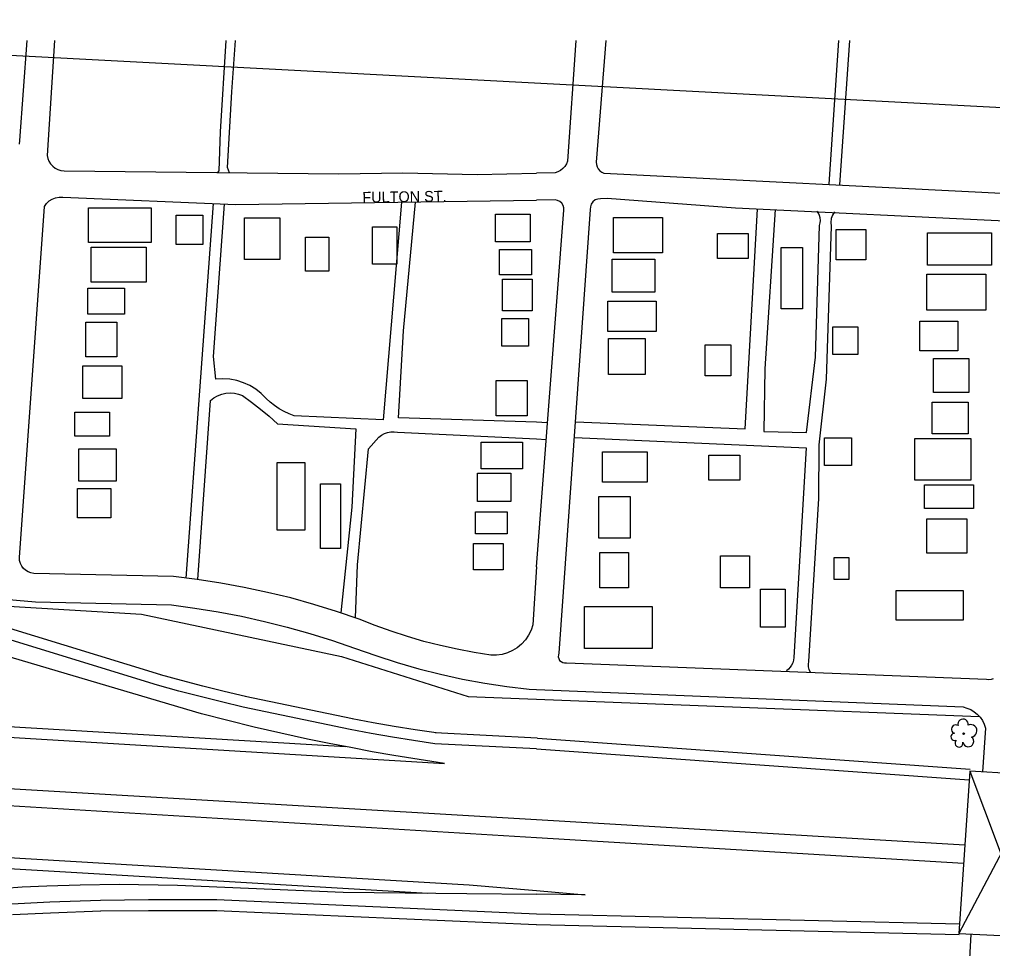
# Model space of a CAD drawing. Extents: x -9648 to 41057, y -12373 to 40276.
# Drawn here: x 16567 to 17468, y -5297 to -4437 of the extents above; entities that cross this region are included whole.
import ezdxf

# ---------------------------------------------------------------- set-up
doc = ezdxf.new("R2010")
doc.units = 0
doc.layers.add('SC_Scratch1', color=7, linetype='Continuous')
doc.layers.add('SH_Data', color=7, linetype='Continuous')

msp = doc.modelspace()

# ---------------------------------------------------------------- linework, layer by layer
at = {"layer": 'SC_Scratch1'}
for p, q in [((17512.22, -4520.66), (15927.4, -4436.94)), ((17447.28, -5132.46), (17504.68, -5286.06)), ((17514.08, -5136.46), (17436.88, -5282.86))]:
    msp.add_line(p, q, dxfattribs=at)
at = {"layer": 'SH_Data'}
for p, q in [((16567.48, -4548.86), (16574.48, -4456.26)), ((16599.68, -4456.26), (16592.88, -4562.66)), ((16758.28, -4456.26), (16753.08, -4540.86)), ((16763.88, -4503.86), (16767.28, -4456.26)), ((17082.28, -4456.26), (17074.68, -4568.06)), ((17110.08, -4456.26), (17101.28, -4568.86)), ((17325.48, -4456.26), (17316.48, -4589.46)), ((17326.68, -4589.96), (17336.08, -4456.26)), ((16759.98, -4573.76), (16763.88, -4503.86)), ((16567.18, -4552.26), (16567.48, -4548.86)), ((16753.08, -4540.86), (16751.88, -4577.06)), ((16592.88, -4562.66), (16593.48, -4565.46)), ((16593.48, -4565.46), (16594.48, -4568.16)), ((16594.48, -4568.16), (16596.08, -4570.66)), ((16596.08, -4570.66), (16597.98, -4572.76)), ((16597.98, -4572.76), (16600.28, -4574.56)), ((16600.28, -4574.56), (16602.88, -4575.86)), ((16602.88, -4575.86), (16605.58, -4576.76)), ((16605.58, -4576.76), (16608.48, -4577.06)), ((16761.58, -4578.76), (16759.98, -4573.76)), ((17068.18, -4576.56), (17065.78, -4577.86)), ((17070.28, -4574.86), (17068.18, -4576.56)), ((17072.08, -4572.86), (17070.28, -4574.86)), ((17073.58, -4570.56), (17072.08, -4572.86)), ((17074.68, -4568.06), (17073.58, -4570.56)), ((17101.28, -4568.86), (17101.48, -4571.06)), ((17101.48, -4571.06), (17102.18, -4573.16)), ((17102.18, -4573.16), (17103.18, -4575.16)), ((17103.18, -4575.16), (17104.68, -4576.86)), ((16608.48, -4577.06), (16862.88, -4579.86)), ((16751.88, -4577.06), (16750.48, -4578.66)), ((16862.88, -4579.86), (16922.28, -4578.86)), ((16922.28, -4578.86), (16991.08, -4580.26)), ((16991.08, -4580.26), (17046.08, -4579.26)), ((17063.28, -4578.86), (17046.08, -4579.26)), ((17065.78, -4577.86), (17063.28, -4578.86)), ((17104.68, -4576.86), (17106.38, -4578.26)), ((17106.38, -4578.26), (17108.38, -4579.16)), ((17108.38, -4579.16), (17494.08, -4598.66)), ((16594.68, -4604.86), (16597.58, -4603.16)), ((16597.58, -4603.16), (16600.68, -4601.96)), ((16600.68, -4601.96), (16603.98, -4601.36)), ((16603.98, -4601.36), (16607.28, -4601.46)), ((16607.28, -4601.46), (16767.68, -4608.26)), ((17102.68, -4603.06), (17100.18, -4603.96)), ((17105.28, -4602.86), (17102.68, -4603.06)), ((17111.28, -4602.66), (17105.28, -4602.86)), ((17230.28, -4611.66), (17111.28, -4602.66)), ((16567.28, -4934.86), (16590.28, -4609.86)), ((16590.28, -4609.86), (16592.28, -4607.16)), ((16592.28, -4607.16), (16594.68, -4604.86)), ((16746.68, -4607.36), (16721.28, -4953.86)), ((16746.88, -4748.66), (16757.08, -4607.86)), ((16767.68, -4608.26), (17046.08, -4604.26)), ((16921.08, -4606.06), (16903.88, -4807.26)), ((16922.88, -4725.06), (16933.88, -4605.96)), ((17063.28, -4603.86), (17046.08, -4604.26)), ((17065.48, -4604.36), (17063.28, -4603.86)), ((17067.58, -4605.46), (17065.48, -4604.36)), ((17069.28, -4607.06), (17067.58, -4605.46)), ((17070.48, -4608.96), (17069.28, -4607.06)), ((17071.18, -4611.16), (17070.48, -4608.96)), ((17071.28, -4613.46), (17071.18, -4611.16)), ((17095.78, -4610.26), (17095.68, -4612.86)), ((17096.58, -4607.76), (17095.78, -4610.26)), ((17098.18, -4605.56), (17096.58, -4607.76)), ((17100.18, -4603.96), (17098.18, -4605.56)), ((17485.88, -4623.96), (17230.28, -4611.66)), ((17239.08, -4815.66), (17250.48, -4612.36)), ((17046.08, -4943.46), (17071.28, -4613.46)), ((17095.68, -4612.86), (17066.68, -5023.26)), ((17266.88, -4612.86), (17257.28, -4760.06)), ((17306.88, -4616.26), (17305.58, -4614.36)), ((17307.88, -4618.36), (17306.88, -4616.26)), ((17308.58, -4620.56), (17307.88, -4618.36)), ((17308.78, -4622.86), (17308.58, -4620.56)), ((17318.78, -4621.16), (17318.38, -4624.66)), ((17319.98, -4617.96), (17318.78, -4621.16)), ((17321.88, -4615.06), (17319.98, -4617.96)), ((17304.28, -4749.46), (17308.08, -4627.46)), ((17308.08, -4627.46), (17308.68, -4625.16)), ((17308.68, -4625.16), (17308.78, -4622.86)), ((17318.68, -4628.06), (17314.08, -4769.66)), ((17318.38, -4624.66), (17318.68, -4628.06)), ((16918.08, -4805.46), (16922.88, -4725.06)), ((16749.08, -4769.66), (16746.88, -4748.66)), ((17295.88, -4819.06), (17304.28, -4749.46)), ((17257.28, -4760.06), (17256.28, -4818.26)), ((16755.58, -4769.36), (16749.08, -4769.66)), ((16761.98, -4769.86), (16755.58, -4769.36)), ((16768.38, -4771.06), (16761.98, -4769.86)), ((16774.58, -4773.06), (16768.38, -4771.06)), ((16780.48, -4775.76), (16774.58, -4773.06)), ((17314.08, -4769.66), (17307.28, -4830.46)), ((16750.68, -4785.16), (16754.48, -4783.76)), ((16754.48, -4783.76), (16758.28, -4782.86)), ((16758.28, -4782.86), (16762.28, -4782.56)), ((16762.28, -4782.56), (16766.28, -4782.76)), ((16766.28, -4782.76), (16770.18, -4783.56)), ((16770.18, -4783.56), (16773.88, -4784.86)), ((16785.98, -4779.16), (16780.48, -4775.76)), ((16791.08, -4783.06), (16785.98, -4779.16)), ((16795.68, -4787.66), (16791.08, -4783.06)), ((16732.28, -4955.16), (16744.08, -4789.46)), ((16744.08, -4789.46), (16747.28, -4787.06)), ((16747.28, -4787.06), (16750.68, -4785.16)), ((16773.88, -4784.86), (16782.18, -4791.06)), ((16782.18, -4791.06), (16790.38, -4797.56)), ((16799.48, -4791.16), (16795.68, -4787.66)), ((16803.48, -4794.26), (16799.48, -4791.16)), ((16790.38, -4797.56), (16798.28, -4804.16)), ((16807.78, -4797.16), (16803.48, -4794.26)), ((16812.28, -4799.66), (16807.78, -4797.16)), ((16816.88, -4801.86), (16812.28, -4799.66)), ((16821.68, -4803.66), (16816.88, -4801.86)), ((16798.28, -4804.16), (16806.08, -4811.06)), ((16903.88, -4807.26), (16821.68, -4803.66)), ((17046.08, -4809.66), (16918.08, -4805.46)), ((17055.88, -4810.06), (17046.08, -4809.66)), ((17082.38, -4809.26), (17239.08, -4815.66)), ((16806.08, -4811.06), (16878.78, -4815.66)), ((16878.78, -4815.66), (16874.88, -4888.26)), ((16905.08, -4820.06), (16908.08, -4819.06)), ((16908.08, -4819.06), (16911.08, -4818.56)), ((16911.08, -4818.56), (16914.18, -4818.46)), ((16914.18, -4818.46), (16917.28, -4818.86)), ((16917.28, -4818.86), (17046.08, -4825.06)), ((17256.28, -4818.26), (17295.88, -4819.06)), ((16890.28, -4834.26), (16899.88, -4823.46)), ((16899.88, -4823.46), (16902.38, -4821.56)), ((16902.38, -4821.56), (16905.08, -4820.06)), ((17046.08, -4825.06), (17054.78, -4825.46)), ((17081.28, -4823.66), (17295.68, -4833.46)), ((16880.08, -4941.46), (16890.28, -4834.26)), ((17295.68, -4833.46), (17284.28, -5027.46)), ((17307.28, -4830.46), (17306.88, -4880.06)), ((17306.88, -4880.06), (17297.88, -5031.06)), ((16874.88, -4888.26), (16864.68, -4986.06)), ((16567.38, -4937.56), (16567.28, -4934.86)), ((16193.48, -4944.86), (16582.08, -4975.66)), ((16568.08, -4940.26), (16567.38, -4937.56)), ((16569.28, -4942.66), (16568.08, -4940.26)), ((16570.88, -4944.86), (16569.28, -4942.66)), ((16572.88, -4946.66), (16570.88, -4944.86)), ((16878.48, -4990.76), (16880.08, -4941.46)), ((17046.08, -4943.46), (17042.48, -4997.06)), ((16575.18, -4948.16), (16572.88, -4946.66)), ((16577.78, -4949.06), (16575.18, -4948.16)), ((16580.48, -4949.46), (16577.78, -4949.06)), ((16709.88, -4952.46), (16580.48, -4949.46)), ((16731.78, -4955.16), (16709.88, -4952.46)), ((16753.68, -4958.46), (16731.78, -4955.16)), ((16775.38, -4962.46), (16753.68, -4958.46)), ((16796.98, -4967.06), (16775.38, -4962.46)), ((16435.85, -4972.35), (16680.32, -4987.24)), ((16818.38, -4972.26), (16796.98, -4967.06)), ((16839.68, -4978.16), (16818.38, -4972.26)), ((16582.08, -4975.66), (16708.08, -4978.66)), ((16708.08, -4978.66), (16729.68, -4981.56)), ((16729.68, -4981.56), (16751.18, -4985.06)), ((16860.78, -4984.76), (16839.68, -4978.16)), ((16680.32, -4987.24), (16865.25, -5026.43)), ((16751.18, -4985.06), (16772.68, -4989.16)), ((16772.68, -4989.16), (16793.98, -4993.86)), ((16881.68, -4991.86), (16860.78, -4984.76)), ((16698.01, -5043.5), (16550.21, -4998.1)), ((16793.98, -4993.86), (16815.08, -4999.16)), ((16815.08, -4999.16), (16836.08, -5005.06)), ((16896.48, -4997.66), (16881.68, -4991.86)), ((16911.38, -5002.96), (16896.48, -4997.66)), ((17042.48, -4997.06), (17040.88, -5001.96)), ((16695.08, -5053.06), (16547.28, -5007.66)), ((16836.08, -5005.06), (16856.98, -5011.56)), ((16926.48, -5007.86), (16911.38, -5002.96)), ((16941.68, -5012.36), (16926.48, -5007.86)), ((17038.58, -5006.66), (17035.68, -5010.96)), ((17040.88, -5001.96), (17038.58, -5006.66)), ((16856.98, -5011.56), (16877.58, -5018.56)), ((16956.98, -5016.26), (16941.68, -5012.36)), ((16972.48, -5019.76), (16956.98, -5016.26)), ((17032.18, -5014.86), (17028.18, -5018.26)), ((17035.68, -5010.96), (17032.18, -5014.86)), ((16735.68, -5079.46), (16553.28, -5025.46)), ((16865.25, -5026.43), (16982.78, -5063.27)), ((16877.58, -5018.56), (16897.18, -5025.56)), ((16897.18, -5025.56), (16916.98, -5031.96)), ((16988.08, -5022.76), (16972.48, -5019.76)), ((17003.68, -5025.26), (16988.08, -5022.76)), ((17008.88, -5025.26), (17003.68, -5025.26)), ((17014.08, -5024.56), (17008.88, -5025.26)), ((17019.08, -5023.06), (17014.08, -5024.56)), ((17023.78, -5020.96), (17019.08, -5023.06)), ((17028.18, -5018.26), (17023.78, -5020.96)), ((17066.18, -5024.96), (17066.08, -5026.66)), ((17066.08, -5026.66), (17066.48, -5028.36)), ((17066.68, -5023.26), (17066.18, -5024.96)), ((16916.98, -5031.96), (16936.98, -5037.66)), ((17066.48, -5028.36), (17067.38, -5029.96)), ((17067.38, -5029.96), (17068.68, -5031.16)), ((17068.68, -5031.16), (17070.18, -5031.96)), ((17070.18, -5031.96), (17071.88, -5032.36)), ((17071.88, -5032.36), (17073.68, -5032.26)), ((17073.68, -5032.26), (17462.68, -5047.46)), ((17280.88, -5036.26), (17279.18, -5038.06)), ((17282.18, -5034.36), (17280.88, -5036.26)), ((17283.18, -5032.16), (17282.18, -5034.36)), ((17283.98, -5029.86), (17283.18, -5032.16)), ((17284.28, -5027.46), (17283.98, -5029.86)), ((17297.88, -5031.06), (17297.48, -5033.46)), ((17297.48, -5033.46), (17297.58, -5035.96)), ((17297.58, -5035.96), (17298.18, -5038.36)), ((16717.37, -5048.71), (16697.67, -5043.41)), ((16936.98, -5037.66), (16957.18, -5042.76)), ((16957.18, -5042.76), (16977.48, -5047.26)), ((17279.18, -5038.06), (17277.28, -5039.56)), ((17298.18, -5038.36), (17299.38, -5040.56)), ((16714.78, -5058.36), (16695.08, -5053.06)), ((16737.07, -5053.78), (16717.27, -5048.68)), ((16756.82, -5058.77), (16737.02, -5053.77)), ((16977.48, -5047.26), (16997.98, -5051.06)), ((16997.98, -5051.06), (17018.58, -5054.16)), ((17018.58, -5054.16), (17039.18, -5056.66)), ((17462.68, -5047.46), (17464.88, -5047.66)), ((17464.88, -5047.66), (17467.08, -5047.46)), ((17467.08, -5047.46), (17469.18, -5046.66)), ((16734.58, -5063.46), (16714.78, -5058.36)), ((16776.62, -5063.54), (16756.72, -5058.74)), ((16982.78, -5063.27), (17455.95, -5081.88)), ((17039.18, -5056.66), (17046.08, -5057.06)), ((17046.08, -5057.06), (17440.88, -5073.06)), ((16191.47, -5069.08), (16868.97, -5109.73)), ((16754.38, -5068.46), (16734.58, -5063.46)), ((16774.28, -5073.26), (16754.38, -5068.46)), ((16875.51, -5084.07), (16776.31, -5063.47)), ((16190.88, -5079.06), (16960.88, -5125.26)), ((16760.18, -5085.66), (16735.68, -5079.46)), ((16873.48, -5093.86), (16774.28, -5073.26)), ((17440.88, -5073.06), (17444.48, -5074.06)), ((17444.48, -5074.06), (17447.98, -5075.56)), ((17447.98, -5075.56), (17451.18, -5077.46)), ((17451.18, -5077.46), (17454.08, -5079.86)), ((17454.08, -5079.86), (17456.68, -5082.66)), ((16784.68, -5091.66), (16760.18, -5085.66)), ((16894.84, -5087.74), (16875.34, -5084.04)), ((16914.24, -5091.22), (16894.74, -5087.72)), ((17456.68, -5082.66), (17458.78, -5085.76)), ((17458.78, -5085.76), (17460.48, -5089.06)), ((17460.48, -5089.06), (17461.68, -5092.66)), ((16809.28, -5097.36), (16784.68, -5091.66)), ((16833.88, -5102.86), (16809.28, -5097.36)), ((16892.98, -5097.56), (16873.48, -5093.86)), ((16912.48, -5101.06), (16892.98, -5097.56)), ((16933.69, -5094.39), (16914.09, -5091.19)), ((16953.09, -5097.16), (16933.49, -5094.36)), ((17046.58, -5101.87), (16952.18, -5097.07)), ((17461.68, -5092.66), (17458.88, -5133.16)), ((16853.88, -5106.86), (16833.88, -5102.86)), ((16873.88, -5110.66), (16853.88, -5106.86)), ((16932.08, -5104.26), (16912.48, -5101.06)), ((16951.68, -5107.06), (16932.08, -5104.26)), ((17046.08, -5111.86), (16951.68, -5107.06)), ((17046.79, -5101.89), (17447.39, -5130.69)), ((16893.88, -5114.46), (16873.88, -5110.66)), ((16913.88, -5118.06), (16893.88, -5114.46)), ((17046.08, -5111.86), (17446.68, -5140.66)), ((17046.08, -5177.66), (16096.88, -5121.66)), ((16960.88, -5125.26), (16913.88, -5118.06)), ((17447.28, -5132.46), (17436.88, -5282.86)), ((17514.08, -5136.46), (17447.28, -5132.46)), ((17046.08, -5194.26), (16282.88, -5148.06)), ((17442.58, -5201.06), (17046.08, -5177.66)), ((16204.28, -5191.66), (16983.68, -5237.56)), ((17441.38, -5218.06), (17046.08, -5194.26)), ((16203.69, -5201.64), (16945.21, -5245.31)), ((16553.48, -5240.86), (16569.68, -5239.46)), ((16569.68, -5239.46), (16592.48, -5238.46)), ((16592.48, -5238.46), (16623.58, -5237.76)), ((16623.58, -5237.76), (16659.48, -5237.06)), ((16659.48, -5237.06), (16713.68, -5237.86)), ((16713.68, -5237.86), (16866.88, -5244.56)), ((16983.68, -5237.56), (17046.08, -5242.96)), ((17046.08, -5242.96), (17090.98, -5246.86)), ((16642.28, -5252.06), (16595.48, -5253.76)), ((16686.68, -5251.66), (16642.28, -5252.06)), ((16725.98, -5251.66), (16686.68, -5251.66)), ((16749.98, -5251.66), (16725.98, -5251.66)), ((17046.08, -5264.76), (16749.98, -5251.66)), ((16866.88, -5244.56), (16981.48, -5245.66)), ((16981.48, -5245.66), (17046.08, -5246.36)), ((17090.98, -5246.86), (17046.08, -5246.36)), ((16595.48, -5253.76), (16560.18, -5255.46)), ((16595.96, -5263.75), (16560.66, -5265.45)), ((16642.64, -5262.06), (16595.84, -5263.76)), ((16686.77, -5261.66), (16642.37, -5262.06)), ((16725.98, -5261.66), (16686.68, -5261.66)), ((16749.98, -5261.66), (16725.98, -5261.66)), ((17045.63, -5274.75), (16749.53, -5261.65)), ((17437.48, -5274.06), (17046.08, -5264.76)), ((17437.24, -5284.06), (17045.84, -5274.76)), ((17436.88, -5282.86), (17504.68, -5286.06)), ((17446.08, -5327.66), (17448.48, -5283.46))]:
    msp.add_line(p, q, dxfattribs=at)
for points in [[(16631.05, -4611.12), (16689.05, -4611.12), (16689.05, -4643.28), (16631.05, -4643.28)], [(16712.38, -4618.05), (16736.97, -4618.05), (16736.97, -4645.17), (16712.38, -4645.17)], [(16775.43, -4620.58), (16808.21, -4620.58), (16808.21, -4659.05), (16775.43, -4659.05)], [(17008, -4617.13), (17039.93, -4617.13), (17039.93, -4642.68), (17008, -4642.68)], [(17117.21, -4620.32), (17162.56, -4620.32), (17162.56, -4652.91), (17117.21, -4652.91)], [(16893.96, -4628.78), (16916.66, -4628.78), (16916.66, -4663.46), (16893.96, -4663.46)], [(16832.17, -4638.24), (16853.61, -4638.24), (16853.61, -4669.77), (16832.17, -4669.77)], [(17213.65, -4635.02), (17241.76, -4635.02), (17241.76, -4658.02), (17213.65, -4658.02)], [(17323.51, -4631.18), (17350.97, -4631.18), (17350.97, -4659.29), (17323.51, -4659.29)], [(17407.82, -4634.38), (17467.21, -4634.38), (17467.21, -4664.41), (17407.82, -4664.41)], [(16633.57, -4647.7), (16684.64, -4647.7), (16684.64, -4679.86), (16633.57, -4679.86)], [(17272.41, -4647.79), (17292.21, -4647.79), (17292.21, -4704.66), (17272.41, -4704.66)], [(17011.83, -4649.71), (17041.21, -4649.71), (17041.21, -4673.35), (17011.83, -4673.35)], [(17115.93, -4658.66), (17155.53, -4658.66), (17155.53, -4689.32), (17115.93, -4689.32)], [(17407.18, -4672.71), (17462.1, -4672.71), (17462.1, -4705.93), (17407.18, -4705.93)], [(17014.38, -4677.18), (17041.85, -4677.18), (17041.85, -4706.57), (17014.38, -4706.57)], [(16630.42, -4685.54), (16664.46, -4685.54), (16664.46, -4709.5), (16630.42, -4709.5)], [(17112.1, -4697.63), (17156.81, -4697.63), (17156.81, -4725.74), (17112.1, -4725.74)], [(16628.53, -4717.07), (16657.53, -4717.07), (16657.53, -4749.24), (16628.53, -4749.24)], [(17013.74, -4713.6), (17038.65, -4713.6), (17038.65, -4739.16), (17013.74, -4739.16)], [(17400.79, -4716.16), (17435.92, -4716.16), (17435.92, -4743.63), (17400.79, -4743.63)], [(17320.32, -4721.27), (17343.31, -4721.27), (17343.31, -4746.82), (17320.32, -4746.82)], [(17112.74, -4732.13), (17146.59, -4732.13), (17146.59, -4765.35), (17112.74, -4765.35)], [(17202.16, -4737.88), (17225.79, -4737.88), (17225.79, -4766.63), (17202.16, -4766.63)], [(17413.56, -4750.66), (17446.14, -4750.66), (17446.14, -4781.96), (17413.56, -4781.96)], [(16626, -4757.44), (16661.94, -4757.44), (16661.94, -4787.71), (16626, -4787.71)], [(17008.64, -4771.1), (17037.38, -4771.1), (17037.38, -4803.69), (17008.64, -4803.69)], [(17412.29, -4790.91), (17445.5, -4790.91), (17445.5, -4820.3), (17412.29, -4820.3)], [(16618.44, -4800.32), (16650.59, -4800.32), (16650.59, -4822.4), (16618.44, -4822.4)], [(16994.58, -4827.96), (17032.91, -4827.96), (17032.91, -4852.88), (16994.58, -4852.88)], [(17312.65, -4824.13), (17337.56, -4824.13), (17337.56, -4849.69), (17312.65, -4849.69)], [(17396.32, -4824.77), (17448.05, -4824.77), (17448.05, -4863.1), (17396.32, -4863.1)], [(16622.22, -4834.38), (16656.9, -4834.38), (16656.9, -4864.02), (16622.22, -4864.02)], [(17106.99, -4836.91), (17148.51, -4836.91), (17148.51, -4865.02), (17106.99, -4865.02)], [(16805.69, -4847), (16831.54, -4847), (16831.54, -4909.43), (16805.69, -4909.43)], [(17205.35, -4840.1), (17234.09, -4840.1), (17234.09, -4863.1), (17205.35, -4863.1)], [(16991.39, -4856.71), (17022.05, -4856.71), (17022.05, -4882.91), (16991.39, -4882.91)], [(16620.96, -4870.96), (16651.85, -4870.96), (16651.85, -4898.08), (16620.96, -4898.08)], [(16846.04, -4866.55), (16864.33, -4866.55), (16864.33, -4926.46), (16846.04, -4926.46)], [(17405.26, -4867.58), (17450.61, -4867.58), (17450.61, -4889.3), (17405.26, -4889.3)], [(17103.8, -4878.44), (17132.54, -4878.44), (17132.54, -4916.77), (17103.8, -4916.77)], [(16989.47, -4892.49), (17018.85, -4892.49), (17018.85, -4912.94), (16989.47, -4912.94)], [(17407.18, -4898.88), (17444.22, -4898.88), (17444.22, -4930.83), (17407.18, -4930.83)], [(16987.56, -4921.88), (17015.02, -4921.88), (17015.02, -4946.16), (16987.56, -4946.16)], [(17104.44, -4930.19), (17131.26, -4930.19), (17131.26, -4962.77), (17104.44, -4962.77)], [(17216.21, -4933.38), (17243.03, -4933.38), (17243.03, -4962.77), (17216.21, -4962.77)], [(17321.59, -4934.66), (17335.01, -4934.66), (17335.01, -4955.11), (17321.59, -4955.11)], [(17253.25, -4964.05), (17276.25, -4964.05), (17276.25, -4999.19), (17253.25, -4999.19)], [(17379.08, -4965.33), (17441.03, -4965.33), (17441.03, -4992.8), (17379.08, -4992.8)], [(17090.39, -4980.02), (17152.98, -4980.02), (17152.98, -5019), (17090.39, -5019)]]:
    msp.add_lwpolyline(points, close=True, dxfattribs=at)
msp.add_circle((17441.43, -5097.89), 0.71, dxfattribs=at)
for centre, radius, start, end in [((17434.04, -5093.61), 3.94, 56.61424, 257.82189), ((17440.92, -5089.13), 4.86, 351.9296, 194.2439), ((17447.92, -5095.17), 5.79, 277.73186, 112.24144), ((17433.02, -5100.8), 3.34, 86.78898, 298.7584), ((17437.12, -5106.51), 3.73, 131.84683, 12.32553), ((17445.71, -5104.93), 5.01, 188.95648, 53.358)]:
    msp.add_arc(centre, radius, start, end, dxfattribs=at)

# ---------------------------------------------------------------- texts
at = {"layer": 'SC_Scratch1'}
msp.add_text('FULTON ST.', height=10, rotation=0.82316, dxfattribs=at).set_placement((16884.77, -4606.5))

doc.saveas('drawing.dxf')
